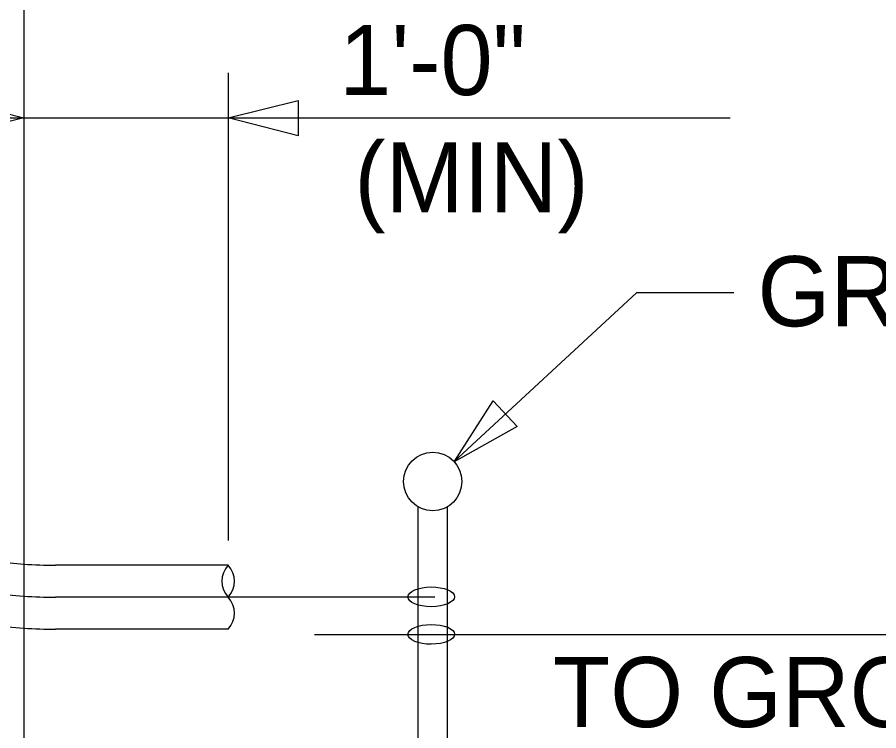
# Model space of a CAD drawing. Extents: x 1299104.8 to 1299141.6, y 239639.8 to 239661.8.
# Drawn here: x 1299112.367 to 1299113.842, y 239649.467 to 239650.688 of the extents above; entities that cross this region are included whole.
import ezdxf

# ---------------------------------------------------------------- set-up
doc = ezdxf.new("R2010")
doc.units = 0
doc.layers.add('DIM TXT', color=7, linetype='Continuous')

msp = doc.modelspace()

# ---------------------------------------------------------------- linework, layer by layer
at = {"layer": 'DIM TXT'}
for p, q in [((1299112.378, 239651.3815), (1299112.378, 239647.9278)), ((1299112.728, 239650.5931), (1299112.728, 239649.7931)), ((1299112.108, 239650.5159), (1299112.378, 239650.5159)), ((1299112.378, 239650.5159), (1299112.728, 239650.5159)), ((1299112.728, 239650.5159), (1299113.5874, 239650.5159)), ((1299113.053, 239649.8505), (1299113.053, 239647.0628)), ((1299113.103, 239649.8505), (1299113.103, 239647.0025)), ((1299112.728, 239649.7505), (1299112.4327, 239649.7505)), ((1299113.0819, 239649.6958), (1299112.4326, 239649.6958)), ((1299112.728, 239649.6412), (1299112.4327, 239649.6412)), ((1299112.8758, 239649.6323), (1299116.2893, 239649.6323))]:
    msp.add_line(p, q, dxfattribs=at)
for points in [[(1299112.2581, 239650.5464), (1299112.378, 239650.5159), (1299112.2578, 239650.4864)], [(1299112.8478, 239650.4854), (1299112.728, 239650.5159), (1299112.8481, 239650.5454)], [(1299113.2229, 239649.9879), (1299113.1151, 239649.9274), (1299113.1818, 239650.0316)]]:
    msp.add_lwpolyline(points, close=True, dxfattribs=at)
msp.add_lwpolyline([(1299113.5938, 239650.2164), (1299113.4274, 239650.2164), (1299113.115, 239649.9278)], dxfattribs=at)
msp.add_circle((1299113.0783, 239649.8939), 0.05, dxfattribs=at)
for centre, radius, start, end in [((1299112.4326, 239650.5005), 0.8047, 180, 266.1034), ((1299112.4327, 239650.5005), 0.8594, 182.3496, 266.3514), ((1299112.4327, 239650.5005), 0.75, 182.4211, 265.8185), ((1299112.4327, 239650.5005), 0.75, 265.8185, 270), ((1299112.7567, 239649.7232), 0.0396, 136.3972, 223.6028), ((1299112.6993, 239649.7232), 0.0396, 316.3972, 43.6028), ((1299112.4327, 239650.5005), 0.8047, 266.1031, 270), ((1299112.6993, 239649.6685), 0.0396, 316.3972, 43.6028), ((1299112.4327, 239650.5005), 0.8594, 266.3514, 270)]:
    msp.add_arc(centre, radius, start, end, dxfattribs=at)
for centre in [(1299113.0758, 239649.6965), (1299113.0758, 239649.6323)]:
    msp.add_ellipse(centre, major_axis=(0.04, 0.0002), ratio=0.421332, dxfattribs=at)

# ---------------------------------------------------------------- texts
for s, p in [('1\'-0"', (1299112.9183, 239650.5549)), ('(MIN)', (1299112.9442, 239650.3542)), ('GROUND ROD A', (1299113.6344, 239650.1593)), ('TO GROUND ROD C', (1299113.2842, 239649.4736))]:
    msp.add_text(s, height=0.12, dxfattribs=at).set_placement(p)

doc.saveas('drawing.dxf')
